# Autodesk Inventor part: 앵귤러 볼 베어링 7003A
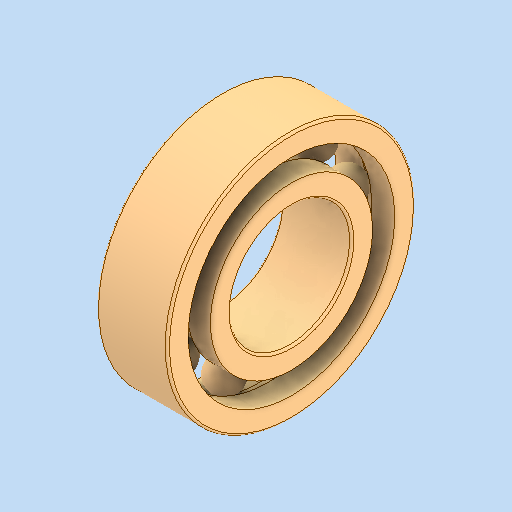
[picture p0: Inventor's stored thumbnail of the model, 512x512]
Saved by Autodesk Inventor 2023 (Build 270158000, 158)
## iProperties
Created: 2024-11
Part Number: 앵귤러 볼 베어링 7003A
Material: 강철, 연강
Description: 앵귤러 콘택트 볼 베어링
Document SubType Name: Modeling
Designer: asung
Density: 7.85 g/cm^3
Appearance: 기본값
Author: jhkim
Sending System: Autodesk Inventor 2025
Preprocessor: ST-DEVELOPER v20
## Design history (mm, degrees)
feature "Solid1"
feature "Solid1:1"
feature "Solid1:2"
feature "Solid1:3"
feature "Solid1:4"
feature "Solid1:5"
feature "Solid1:6"
feature "Solid1:7"
feature "Solid1:8"
feature "Solid1:9"
feature "Solid1:10"
node "솔리드1"
node "솔리드2"
node "솔리드3"
node "솔리드4"
node "솔리드5"
node "솔리드6"
node "솔리드7"
node "솔리드8"
node "솔리드9"
node "솔리드10"
node "솔리드11"
